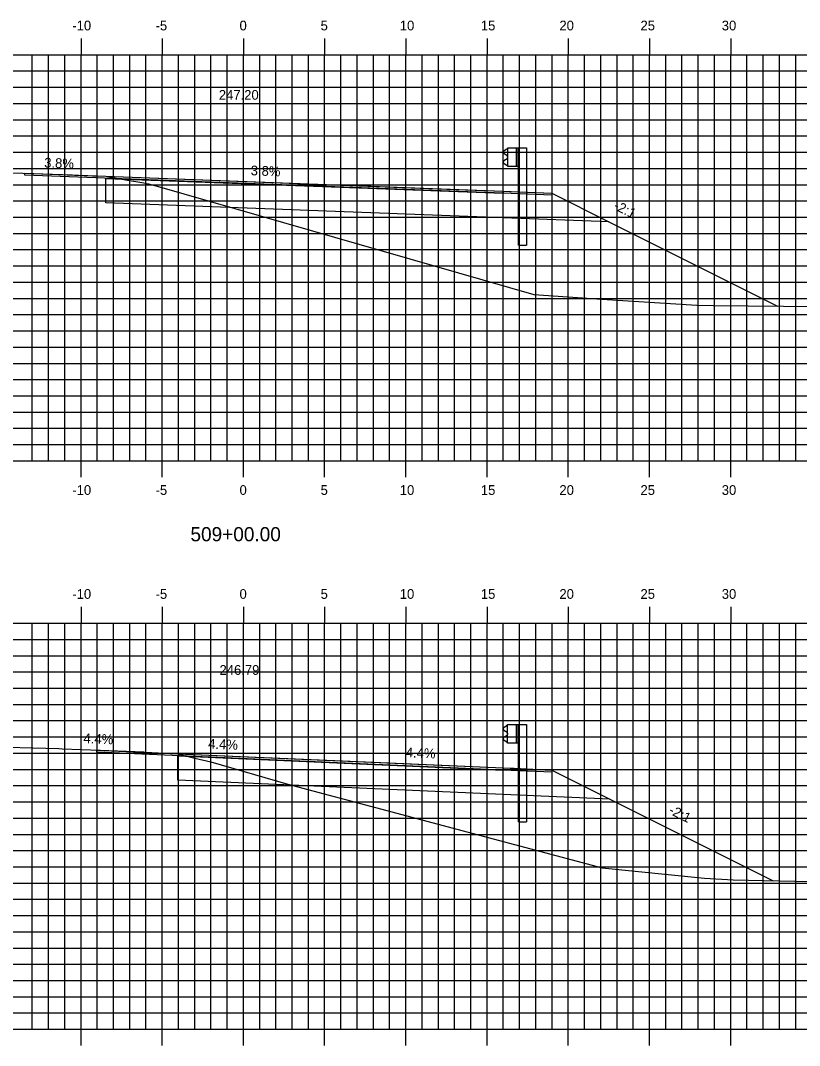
# Model space of a CAD drawing. Extents: x 1170543 to 1177585, y 609599 to 610623.
# Drawn here: x 1172165 to 1172213, y 610311.8 to 610374.9 of the extents above; entities that cross this region are included whole.
import ezdxf

# ---------------------------------------------------------------- set-up
doc = ezdxf.new("R2010")
doc.units = 0
for name, color, linetype in [('ANNOTATION', 7, 'Continuous'), ('D_Guardrail_Beam_Rt', 7, 'Continuous'), ('D_Roadway_Centerline', 7, 'Continuous'), ('D_Roadway_Centerline_Text', 7, 'Continuous'), ('D_Roadway_Edge_TW', 7, 'Continuous'), ('D_Roadway_SubGrade', 7, 'Continuous'), ('H_V ANNOTATION', 7, 'Continuous'), ('MAJOR', 7, 'Continuous'), ('MINOR', 7, 'Continuous'), ('S_Roadway_Centerline', 7, 'Continuous')]:
    doc.layers.add(name, color=color, linetype=linetype)

msp = doc.modelspace()

# ---------------------------------------------------------------- linework, layer by layer
at = {"layer": 'D_Guardrail_Beam_Rt'}
for p, q in [((1172194.945, 610366.975), (1172194.801, 610366.875)), ((1172195.035, 610366.996), (1172194.961, 610366.981)), ((1172195.035, 610367.079), (1172195.722, 610367.079)), ((1172195.035, 610365.913), (1172195.035, 610367.079)), ((1172195.556, 610367.079), (1172195.556, 610365.913)), ((1172195.66, 610367.079), (1172195.66, 610365.913)), ((1172195.722, 610367.079), (1172196.193, 610367.079)), ((1172195.722, 610367.079), (1172195.722, 610365.913)), ((1172196.193, 610367.079), (1172196.193, 610361.079)), ((1172194.801, 610366.732), (1172194.997, 610366.595)), ((1172194.997, 610366.396), (1172194.801, 610366.26)), ((1172195.03, 610366.531), (1172195.03, 610366.461)), ((1172194.801, 610366.117), (1172194.945, 610366.017)), ((1172194.961, 610366.011), (1172195.035, 610365.996)), ((1172195.722, 610365.913), (1172195.035, 610365.913)), ((1172195.701, 610361.079), (1172195.701, 610365.913)), ((1172195.701, 610361.079), (1172196.193, 610361.079)), ((1172194.944, 610331.468), (1172194.801, 610331.368)), ((1172195.034, 610331.489), (1172194.96, 610331.475)), ((1172195.034, 610331.573), (1172195.722, 610331.573)), ((1172195.034, 610330.406), (1172195.034, 610331.573)), ((1172195.555, 610331.573), (1172195.555, 610330.406)), ((1172195.659, 610331.573), (1172195.659, 610330.406)), ((1172195.722, 610331.573), (1172196.193, 610331.573)), ((1172195.722, 610331.573), (1172195.722, 610330.406)), ((1172196.193, 610331.573), (1172196.193, 610325.573)), ((1172194.801, 610331.225), (1172194.996, 610331.089)), ((1172194.996, 610330.89), (1172194.801, 610330.754)), ((1172195.03, 610331.025), (1172195.03, 610330.954)), ((1172194.801, 610330.611), (1172194.944, 610330.511)), ((1172194.96, 610330.504), (1172195.034, 610330.489)), ((1172195.722, 610330.406), (1172195.034, 610330.406)), ((1172195.701, 610325.573), (1172195.701, 610330.406)), ((1172195.701, 610325.573), (1172196.193, 610325.573))]:
    msp.add_line(p, q, dxfattribs=at)
for centre, major_axis, start_param, end_param in [((1172194.852, 610366.803), (-0.0877, 0), 5.323254, 7.243116), ((1172194.969, 610366.941), (-0.0417, 0), 4.907132, 5.323254), ((1172194.852, 610366.189), (-0.0877, 0), 5.323254, 7.243116), ((1172194.951, 610366.531), (0.0789, 0), 0, 0.959931), ((1172194.951, 610366.461), (0.0789, 0), 5.323254, 6.283185), ((1172194.969, 610366.051), (-0.0417, 0), 0.959931, 1.376053), ((1172194.968, 610331.434), (-0.0417, 0), 4.907132, 5.323254), ((1172194.851, 610331.297), (-0.0877, 0), 5.323254, 7.243116), ((1172194.951, 610331.025), (0.0789, 0), 0, 0.959931), ((1172194.951, 610330.954), (0.0789, 0), 5.323254, 6.283185), ((1172194.851, 610330.682), (-0.0877, 0), 5.323254, 7.243116), ((1172194.968, 610330.545), (-0.0417, 0), 0.959931, 1.376053)]:
    msp.add_ellipse(centre, major_axis=major_axis, ratio=0.995501, start_param=start_param, end_param=end_param, dxfattribs=at)
at = {"layer": 'D_Roadway_Centerline'}
for points in [[(1172165.314, 610365.506), (1172169.479, 610365.348), (1172169.634, 610365.342), (1172169.658, 610365.342), (1172170.299, 610365.317), (1172190.722, 610364.547), (1172194.764, 610364.394), (1172195.172, 610364.385), (1172197.751, 610364.28), (1172201.271, 610362.52), (1172211.65, 610357.33)], [(1172169.742, 610329.986), (1172169.938, 610329.977), (1172169.97, 610329.976), (1172170.643, 610329.946), (1172174.722, 610329.767), (1172184.387, 610329.342), (1172194.764, 610328.887), (1172195.436, 610328.873), (1172197.753, 610328.756), (1172197.753, 610328.756), (1172201.315, 610326.975), (1172211.38, 610321.943)]]:
    msp.add_lwpolyline(points, dxfattribs=at)
at = {"layer": 'D_Roadway_Edge_TW'}
for points in [[(1172165.314, 610365.506), (1172170.299, 610365.317), (1172194.764, 610364.394), (1172194.764, 610364.269), (1172165.314, 610365.381), (1172165.314, 610365.506)], [(1172165.314, 610365.506), (1172170.299, 610365.317), (1172194.764, 610364.394), (1172194.764, 610364.269), (1172165.314, 610365.381), (1172165.314, 610365.506)], [(1172169.742, 610329.986), (1172174.722, 610329.767), (1172194.764, 610328.887), (1172194.764, 610328.762), (1172169.742, 610329.861), (1172169.742, 610329.986)], [(1172169.742, 610329.986), (1172174.722, 610329.767), (1172194.764, 610328.887), (1172194.764, 610328.762), (1172169.742, 610329.861), (1172169.742, 610329.986)]]:
    msp.add_lwpolyline(points, dxfattribs=at)
for points in [[(1172165.314, 610365.506), (1172170.299, 610365.317), (1172194.764, 610364.394), (1172197.751, 610364.28), (1172197.751, 610364.156), (1172194.764, 610364.269), (1172165.314, 610365.381)], [(1172169.742, 610329.986), (1172174.722, 610329.767), (1172194.764, 610328.887), (1172197.753, 610328.756), (1172197.753, 610328.631), (1172194.764, 610328.762), (1172169.742, 610329.861)]]:
    msp.add_lwpolyline(points, close=True, dxfattribs=at)
at = {"layer": 'D_Roadway_SubGrade'}
for points in [[(1172194.764, 610364.394), (1172197.751, 610364.28), (1172201.271, 610362.52), (1172194.764, 610362.769), (1172170.299, 610363.692), (1172170.299, 610365.192), (1172194.764, 610364.269)], [(1172194.764, 610364.394), (1172197.751, 610364.28), (1172201.271, 610362.52), (1172194.764, 610362.769), (1172170.299, 610363.692), (1172170.299, 610365.192), (1172194.764, 610364.269)], [(1172194.764, 610328.887), (1172197.753, 610328.756), (1172201.315, 610326.975), (1172194.764, 610327.262), (1172174.722, 610328.142), (1172174.722, 610329.642), (1172194.764, 610328.762)]]:
    msp.add_lwpolyline(points, close=True, dxfattribs=at)
at = {"layer": 'MAJOR'}
for p, q in [((1172168.767, 610373.803), (1172168.767, 610372.801)), ((1172173.767, 610373.803), (1172173.767, 610372.801)), ((1172178.767, 610373.803), (1172178.767, 610372.801)), ((1172183.767, 610373.803), (1172183.767, 610372.801)), ((1172188.767, 610373.803), (1172188.767, 610372.801)), ((1172193.767, 610373.803), (1172193.767, 610372.801)), ((1172198.767, 610373.803), (1172198.767, 610372.801)), ((1172203.767, 610373.803), (1172203.767, 610372.801)), ((1172208.767, 610373.803), (1172208.767, 610372.801)), ((1172108.767, 610372.801), (1172248.767, 610372.801)), ((1172108.767, 610372.801), (1172248.767, 610372.801)), ((1172168.767, 610347.801), (1172168.767, 610372.801)), ((1172173.767, 610347.801), (1172173.767, 610372.801)), ((1172178.767, 610347.801), (1172178.767, 610372.801)), ((1172183.767, 610347.801), (1172183.767, 610372.801)), ((1172188.767, 610347.801), (1172188.767, 610372.801)), ((1172193.767, 610347.801), (1172193.767, 610372.801)), ((1172198.767, 610347.801), (1172198.767, 610372.801)), ((1172203.767, 610347.801), (1172203.767, 610372.801)), ((1172208.767, 610347.801), (1172208.767, 610372.801)), ((1172108.767, 610367.801), (1172248.767, 610367.801)), ((1172108.767, 610362.801), (1172248.767, 610362.801)), ((1172108.767, 610357.801), (1172248.767, 610357.801)), ((1172108.767, 610352.801), (1172248.767, 610352.801)), ((1172108.767, 610347.801), (1172248.767, 610347.801)), ((1172108.767, 610347.801), (1172248.767, 610347.801)), ((1172168.767, 610346.799), (1172168.767, 610347.801)), ((1172173.767, 610346.799), (1172173.767, 610347.801)), ((1172178.767, 610346.799), (1172178.767, 610347.801)), ((1172183.767, 610346.799), (1172183.767, 610347.801)), ((1172188.767, 610346.799), (1172188.767, 610347.801)), ((1172193.767, 610346.799), (1172193.767, 610347.801)), ((1172198.767, 610346.799), (1172198.767, 610347.801)), ((1172203.767, 610346.799), (1172203.767, 610347.801)), ((1172208.767, 610346.799), (1172208.767, 610347.801)), ((1172168.767, 610338.803), (1172168.767, 610337.801)), ((1172173.767, 610338.803), (1172173.767, 610337.801)), ((1172178.767, 610338.803), (1172178.767, 610337.801)), ((1172183.767, 610338.803), (1172183.767, 610337.801)), ((1172188.767, 610338.803), (1172188.767, 610337.801)), ((1172193.767, 610338.803), (1172193.767, 610337.801)), ((1172198.767, 610338.803), (1172198.767, 610337.801)), ((1172203.767, 610338.803), (1172203.767, 610337.801)), ((1172208.767, 610338.803), (1172208.767, 610337.801)), ((1172108.767, 610337.801), (1172248.767, 610337.801)), ((1172108.767, 610337.801), (1172248.767, 610337.801)), ((1172168.767, 610312.801), (1172168.767, 610337.801)), ((1172173.767, 610312.801), (1172173.767, 610337.801)), ((1172178.767, 610312.801), (1172178.767, 610337.801)), ((1172183.767, 610312.801), (1172183.767, 610337.801)), ((1172188.767, 610312.801), (1172188.767, 610337.801)), ((1172193.767, 610312.801), (1172193.767, 610337.801)), ((1172198.767, 610312.801), (1172198.767, 610337.801)), ((1172203.767, 610312.801), (1172203.767, 610337.801)), ((1172208.767, 610312.801), (1172208.767, 610337.801)), ((1172108.767, 610332.801), (1172248.767, 610332.801)), ((1172108.767, 610327.801), (1172248.767, 610327.801)), ((1172108.767, 610322.801), (1172248.767, 610322.801)), ((1172108.767, 610317.801), (1172248.767, 610317.801)), ((1172108.767, 610312.801), (1172248.767, 610312.801)), ((1172108.767, 610312.801), (1172248.767, 610312.801)), ((1172168.767, 610311.799), (1172168.767, 610312.801)), ((1172173.767, 610311.799), (1172173.767, 610312.801)), ((1172178.767, 610311.799), (1172178.767, 610312.801)), ((1172183.767, 610311.799), (1172183.767, 610312.801)), ((1172188.767, 610311.799), (1172188.767, 610312.801)), ((1172193.767, 610311.799), (1172193.767, 610312.801)), ((1172198.767, 610311.799), (1172198.767, 610312.801)), ((1172203.767, 610311.799), (1172203.767, 610312.801)), ((1172208.767, 610311.799), (1172208.767, 610312.801))]:
    msp.add_line(p, q, dxfattribs=at)
at = {"layer": 'MINOR'}
for p, q in [((1172165.767, 610347.801), (1172165.767, 610372.801)), ((1172166.767, 610347.801), (1172166.767, 610372.801)), ((1172167.767, 610347.801), (1172167.767, 610372.801)), ((1172169.767, 610347.801), (1172169.767, 610372.801)), ((1172170.767, 610347.801), (1172170.767, 610372.801)), ((1172171.767, 610347.801), (1172171.767, 610372.801)), ((1172172.767, 610347.801), (1172172.767, 610372.801)), ((1172174.767, 610347.801), (1172174.767, 610372.801)), ((1172175.767, 610347.801), (1172175.767, 610372.801)), ((1172176.767, 610347.801), (1172176.767, 610372.801)), ((1172177.767, 610347.801), (1172177.767, 610372.801)), ((1172179.767, 610347.801), (1172179.767, 610372.801)), ((1172180.767, 610347.801), (1172180.767, 610372.801)), ((1172181.767, 610347.801), (1172181.767, 610372.801)), ((1172182.767, 610347.801), (1172182.767, 610372.801)), ((1172184.767, 610347.801), (1172184.767, 610372.801)), ((1172185.767, 610347.801), (1172185.767, 610372.801)), ((1172186.767, 610347.801), (1172186.767, 610372.801)), ((1172187.767, 610347.801), (1172187.767, 610372.801)), ((1172189.767, 610347.801), (1172189.767, 610372.801)), ((1172190.767, 610347.801), (1172190.767, 610372.801)), ((1172191.767, 610347.801), (1172191.767, 610372.801)), ((1172192.767, 610347.801), (1172192.767, 610372.801)), ((1172194.767, 610347.801), (1172194.767, 610372.801)), ((1172195.767, 610347.801), (1172195.767, 610372.801)), ((1172196.767, 610347.801), (1172196.767, 610372.801)), ((1172197.767, 610347.801), (1172197.767, 610372.801)), ((1172199.767, 610347.801), (1172199.767, 610372.801)), ((1172200.767, 610347.801), (1172200.767, 610372.801)), ((1172201.767, 610347.801), (1172201.767, 610372.801)), ((1172202.767, 610347.801), (1172202.767, 610372.801)), ((1172204.767, 610347.801), (1172204.767, 610372.801)), ((1172205.767, 610347.801), (1172205.767, 610372.801)), ((1172206.767, 610347.801), (1172206.767, 610372.801)), ((1172207.767, 610347.801), (1172207.767, 610372.801)), ((1172209.767, 610347.801), (1172209.767, 610372.801)), ((1172210.767, 610347.801), (1172210.767, 610372.801)), ((1172211.767, 610347.801), (1172211.767, 610372.801)), ((1172212.767, 610347.801), (1172212.767, 610372.801)), ((1172108.767, 610371.801), (1172248.767, 610371.801)), ((1172108.767, 610370.801), (1172248.767, 610370.801)), ((1172108.767, 610369.801), (1172248.767, 610369.801)), ((1172108.767, 610368.801), (1172248.767, 610368.801)), ((1172108.767, 610366.801), (1172248.767, 610366.801)), ((1172108.767, 610365.801), (1172248.767, 610365.801)), ((1172108.767, 610364.801), (1172248.767, 610364.801)), ((1172108.767, 610363.801), (1172248.767, 610363.801)), ((1172108.767, 610361.801), (1172248.767, 610361.801)), ((1172108.767, 610360.801), (1172248.767, 610360.801)), ((1172108.767, 610359.801), (1172248.767, 610359.801)), ((1172108.767, 610358.801), (1172248.767, 610358.801)), ((1172108.767, 610356.801), (1172248.767, 610356.801)), ((1172108.767, 610355.801), (1172248.767, 610355.801)), ((1172108.767, 610354.801), (1172248.767, 610354.801)), ((1172108.767, 610353.801), (1172248.767, 610353.801)), ((1172108.767, 610351.801), (1172248.767, 610351.801)), ((1172108.767, 610350.801), (1172248.767, 610350.801)), ((1172108.767, 610349.801), (1172248.767, 610349.801)), ((1172108.767, 610348.801), (1172248.767, 610348.801)), ((1172165.767, 610312.801), (1172165.767, 610337.801)), ((1172166.767, 610312.801), (1172166.767, 610337.801)), ((1172167.767, 610312.801), (1172167.767, 610337.801)), ((1172169.767, 610312.801), (1172169.767, 610337.801)), ((1172170.767, 610312.801), (1172170.767, 610337.801)), ((1172171.767, 610312.801), (1172171.767, 610337.801)), ((1172172.767, 610312.801), (1172172.767, 610337.801)), ((1172174.767, 610312.801), (1172174.767, 610337.801)), ((1172175.767, 610312.801), (1172175.767, 610337.801)), ((1172176.767, 610312.801), (1172176.767, 610337.801)), ((1172177.767, 610312.801), (1172177.767, 610337.801)), ((1172179.767, 610312.801), (1172179.767, 610337.801)), ((1172180.767, 610312.801), (1172180.767, 610337.801)), ((1172181.767, 610312.801), (1172181.767, 610337.801)), ((1172182.767, 610312.801), (1172182.767, 610337.801)), ((1172184.767, 610312.801), (1172184.767, 610337.801)), ((1172185.767, 610312.801), (1172185.767, 610337.801)), ((1172186.767, 610312.801), (1172186.767, 610337.801)), ((1172187.767, 610312.801), (1172187.767, 610337.801)), ((1172189.767, 610312.801), (1172189.767, 610337.801)), ((1172190.767, 610312.801), (1172190.767, 610337.801)), ((1172191.767, 610312.801), (1172191.767, 610337.801)), ((1172192.767, 610312.801), (1172192.767, 610337.801)), ((1172194.767, 610312.801), (1172194.767, 610337.801)), ((1172195.767, 610312.801), (1172195.767, 610337.801)), ((1172196.767, 610312.801), (1172196.767, 610337.801)), ((1172197.767, 610312.801), (1172197.767, 610337.801)), ((1172199.767, 610312.801), (1172199.767, 610337.801)), ((1172200.767, 610312.801), (1172200.767, 610337.801)), ((1172201.767, 610312.801), (1172201.767, 610337.801)), ((1172202.767, 610312.801), (1172202.767, 610337.801)), ((1172204.767, 610312.801), (1172204.767, 610337.801)), ((1172205.767, 610312.801), (1172205.767, 610337.801)), ((1172206.767, 610312.801), (1172206.767, 610337.801)), ((1172207.767, 610312.801), (1172207.767, 610337.801)), ((1172209.767, 610312.801), (1172209.767, 610337.801)), ((1172210.767, 610312.801), (1172210.767, 610337.801)), ((1172211.767, 610312.801), (1172211.767, 610337.801)), ((1172212.767, 610312.801), (1172212.767, 610337.801)), ((1172108.767, 610336.801), (1172248.767, 610336.801)), ((1172108.767, 610335.801), (1172248.767, 610335.801)), ((1172108.767, 610334.801), (1172248.767, 610334.801)), ((1172108.767, 610333.801), (1172248.767, 610333.801)), ((1172108.767, 610331.801), (1172248.767, 610331.801)), ((1172108.767, 610330.801), (1172248.767, 610330.801)), ((1172108.767, 610329.801), (1172248.767, 610329.801)), ((1172108.767, 610328.801), (1172248.767, 610328.801)), ((1172108.767, 610326.801), (1172248.767, 610326.801)), ((1172108.767, 610325.801), (1172248.767, 610325.801)), ((1172108.767, 610324.801), (1172248.767, 610324.801)), ((1172108.767, 610323.801), (1172248.767, 610323.801)), ((1172108.767, 610321.801), (1172248.767, 610321.801)), ((1172108.767, 610320.801), (1172248.767, 610320.801)), ((1172108.767, 610319.801), (1172248.767, 610319.801)), ((1172108.767, 610318.801), (1172248.767, 610318.801)), ((1172108.767, 610316.801), (1172248.767, 610316.801)), ((1172108.767, 610315.801), (1172248.767, 610315.801)), ((1172108.767, 610314.801), (1172248.767, 610314.801)), ((1172108.767, 610313.801), (1172248.767, 610313.801))]:
    msp.add_line(p, q, dxfattribs=at)
at = {"layer": 'S_Roadway_Centerline'}
for points in [[(1172163.342, 610365.579), (1172168.235, 610365.398), (1172168.361, 610365.393), (1172168.535, 610365.387), (1172170.299, 610365.317), (1172171.502, 610365.105), (1172172.636, 610364.907), (1172172.764, 610364.885), (1172172.781, 610364.882), (1172172.92, 610364.861), (1172173.606, 610364.674), (1172196.652, 610358.032), (1172200.835, 610357.76), (1172206.677, 610357.391), (1172207.68, 610357.369), (1172244.485, 610357.008), (1172248.767, 610357.013)], [(1172162.594, 610330.208), (1172167.405, 610330.076), (1172167.611, 610330.07), (1172169.943, 610329.978), (1172172.627, 610329.872), (1172172.717, 610329.868), (1172174.722, 610329.767), (1172175.285, 610329.612), (1172175.771, 610329.488), (1172176.75, 610329.256), (1172181.508, 610327.883), (1172200.846, 610322.73), (1172207.161, 610322.107), (1172208.918, 610321.997), (1172230.709, 610321.519), (1172240.248, 610321.427), (1172248.13, 610321.437), (1172248.767, 610321.422)]]:
    msp.add_lwpolyline(points, dxfattribs=at)

# ---------------------------------------------------------------- texts
at = {"layer": 'ANNOTATION'}
for s, rotation, p in [('3.8%', 357.83493, (1172166.491, 610365.862)), ('3.8%', 357.84081, (1172179.207, 610365.382)), ('-2:1', 333.32913, (1172201.512, 610363.323)), ('4.4%', 357.47862, (1172168.911, 610330.423)), ('4.4%', 357.48395, (1172176.586, 610330.086)), ('-4.4%', 357.48825, (1172188.486, 610329.563)), ('-2:1', 333.32913, (1172204.899, 610326.108))]:
    msp.add_text(s, height=0.6, rotation=rotation, dxfattribs=at).set_placement(p)
at = {"layer": 'D_Roadway_Centerline_Text'}
for s, p in [('247.20', (1172177.252, 610370.03)), ('246.79', (1172177.295, 610334.621))]:
    msp.add_text(s, height=0.6, dxfattribs=at).set_placement(p)
at = {"layer": 'H_V ANNOTATION'}
for s, height, p in [('-10', 0.6, (1172168.232, 610374.301)), ('-5', 0.6, (1172173.358, 610374.301)), ('0', 0.6, (1172178.526, 610374.301)), ('5', 0.6, (1172183.518, 610374.301)), ('10', 0.6, (1172188.392, 610374.301)), ('15', 0.6, (1172193.384, 610374.301)), ('20', 0.6, (1172198.221, 610374.301)), ('25', 0.6, (1172203.213, 610374.301)), ('30', 0.6, (1172208.216, 610374.301)), ('-10', 0.6, (1172168.232, 610345.701)), ('-5', 0.6, (1172173.358, 610345.701)), ('0', 0.6, (1172178.526, 610345.701)), ('5', 0.6, (1172183.518, 610345.701)), ('10', 0.6, (1172188.392, 610345.701)), ('15', 0.6, (1172193.384, 610345.701)), ('20', 0.6, (1172198.221, 610345.701)), ('25', 0.6, (1172203.213, 610345.701)), ('30', 0.6, (1172208.216, 610345.701)), ('509+00.00', 0.875, (1172175.505, 610342.844)), ('-10', 0.6, (1172168.232, 610339.301)), ('-5', 0.6, (1172173.358, 610339.301)), ('0', 0.6, (1172178.526, 610339.301)), ('5', 0.6, (1172183.518, 610339.301)), ('10', 0.6, (1172188.392, 610339.301)), ('15', 0.6, (1172193.384, 610339.301)), ('20', 0.6, (1172198.221, 610339.301)), ('25', 0.6, (1172203.213, 610339.301)), ('30', 0.6, (1172208.216, 610339.301))]:
    msp.add_text(s, height=height, dxfattribs=at).set_placement(p)

doc.saveas('drawing.dxf')
